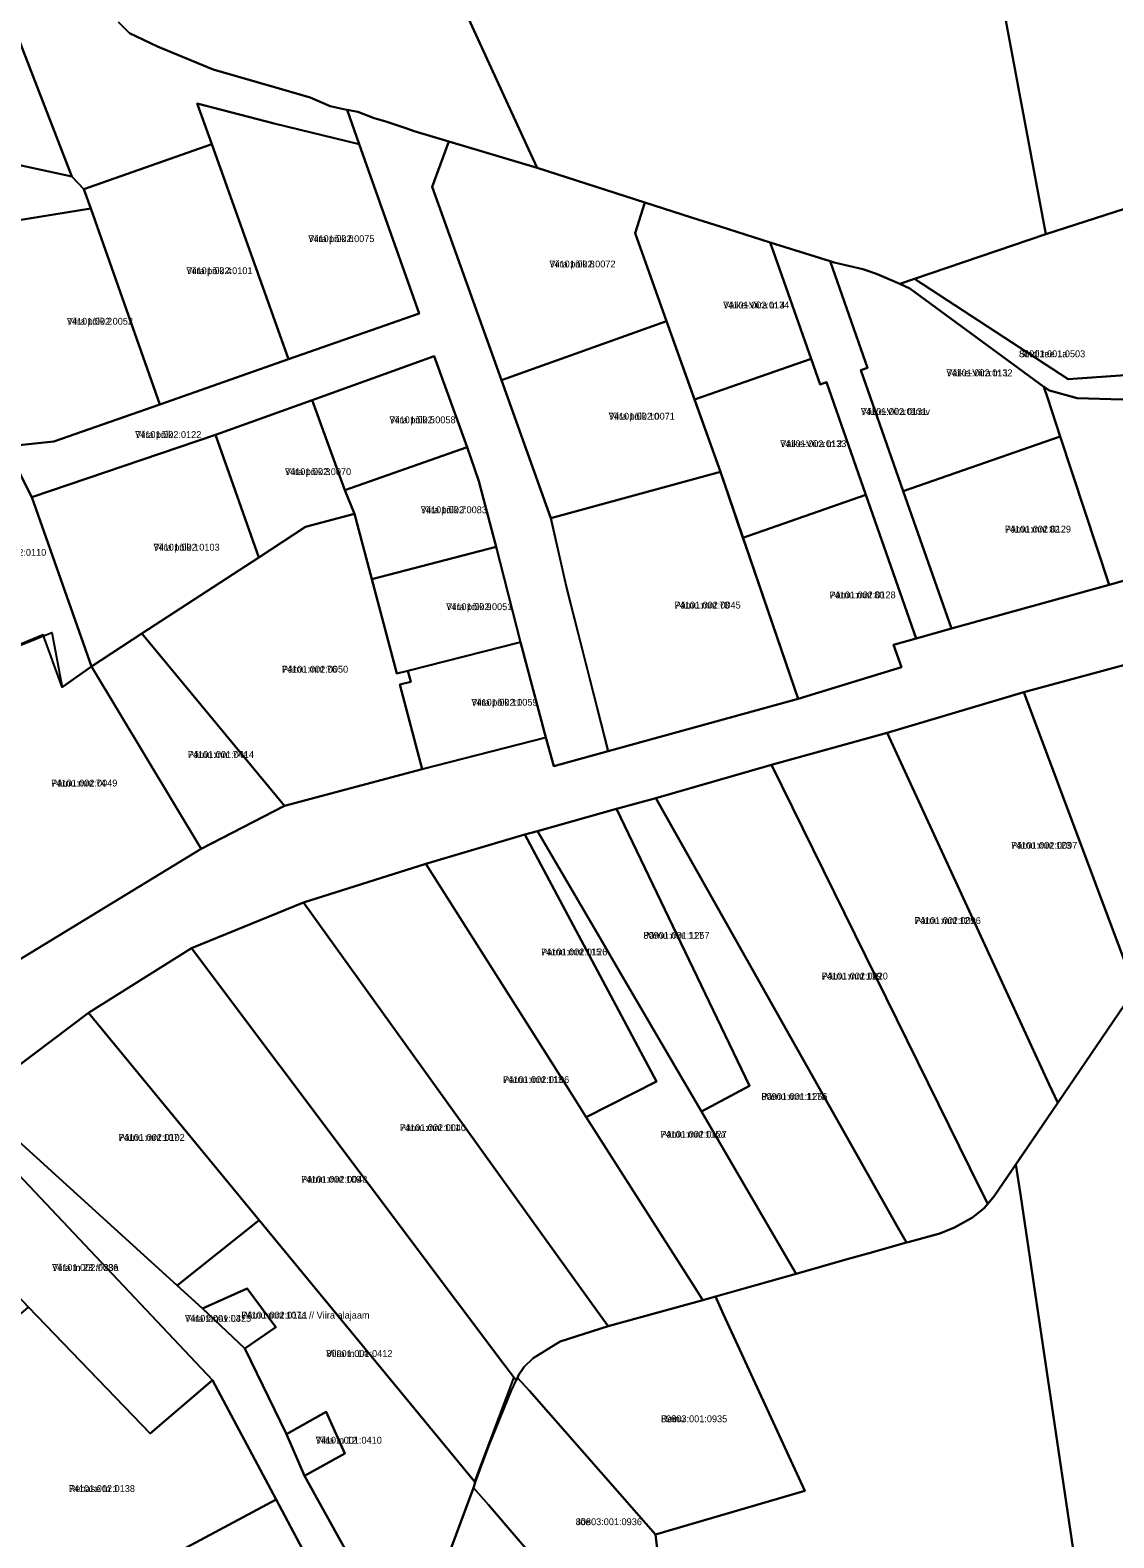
# Model space of a CAD drawing. Extents: x 524000 to 564260, y 6469338 to 6496391.
# Drawn here: x 539565.4 to 539802.9, y 6475121.9 to 6475452.4 of the extents above; entities that cross this region are included whole.
import ezdxf

# ---------------------------------------------------------------- set-up
doc = ezdxf.new("R2010")
doc.units = 0
for name, color, linetype in [('L_AADRESS', 7, 'Continuous'), ('PIIR', 7, 'Continuous'), ('TUNNUS', 7, 'Continuous')]:
    doc.layers.add(name, color=color, linetype=linetype)

msp = doc.modelspace()

# ---------------------------------------------------------------- linework, layer by layer
at = {"layer": 'PIIR'}
for points in [[(539758.44, 6475565.74), (539788.06, 6475407.65), (539759.28, 6475397.84), (539756, 6475396.72), (539750.91, 6475398.95), (539747.94, 6475399.94), (539741.65, 6475401.41), (539740.75, 6475401.69), (539727.65, 6475405.84), (539716.68, 6475409.31), (539713.15, 6475410.42), (539710.4, 6475411.29), (539700.11, 6475414.6), (539676.52, 6475422.21), (539674.67, 6475426.25), (539632.78, 6475517.5)], [(539944.83, 6475550.52), (539939.93, 6475424.76), (539893.58, 6475425.97), (539843.89, 6475430.55), (539837.9, 6475423.73), (539788.06, 6475407.65), (539758.44, 6475565.74)], [(539632.78, 6475517.5), (539674.67, 6475426.25), (539676.52, 6475422.21), (539657.18, 6475427.97), (539649.61, 6475430.22), (539647.73, 6475430.87), (539646.89, 6475431.16), (539645.11, 6475431.77), (539643.36, 6475432.37), (539640.79, 6475433.04), (539637.22, 6475434.42), (539634.87, 6475434.87), (539634.08, 6475435.02), (539631.18, 6475435.72), (539626.79, 6475437.63), (539620, 6475439.58), (539605.5, 6475443.71), (539593.35, 6475448.75), (539587.21, 6475451.69), (539584.75, 6475454.08)], [(539584.75, 6475454.08), (539587.21, 6475451.69), (539593.35, 6475448.75), (539605.5, 6475443.71), (539620, 6475439.58), (539626.79, 6475437.63), (539631.18, 6475435.72), (539634.08, 6475435.02), (539634.87, 6475434.87), (539637.56, 6475427.34), (539618.91, 6475431.9), (539602.06, 6475436.31), (539605.25, 6475427.37), (539577.22, 6475417.54), (539574.57, 6475420.29), (539559.71, 6475458.6)], [(539562.28, 6475361.31), (539570.64, 6475362.17), (539593.81, 6475370.3), (539622.08, 6475380.22), (539650.69, 6475390.25), (539637.56, 6475427.34), (539634.87, 6475434.87), (539637.22, 6475434.42), (539640.79, 6475433.04), (539643.36, 6475432.37), (539645.11, 6475431.77), (539646.89, 6475431.16), (539647.73, 6475430.87), (539649.61, 6475430.22), (539657.18, 6475427.97), (539653.52, 6475418.02), (539668.74, 6475375.62), (539679.57, 6475345.43), (539683.08, 6475329.78), (539692.11, 6475294.35), (539680.22, 6475291.07), (539678.43, 6475297.31), (539672.92, 6475318.2), (539667.57, 6475339.12), (539663.79, 6475353.49), (539661.17, 6475360.93), (539654, 6475380.89), (539627.2, 6475371.27), (539606.06, 6475363.69), (539565.76, 6475349.97), (539560.27, 6475360.93)], [(539557.87, 6475245.52), (539602.92, 6475272.93), (539621.14, 6475282.34), (539651.35, 6475290.37), (539678.43, 6475297.31), (539680.22, 6475291.07), (539692.11, 6475294.35), (539733.73, 6475305.77), (539756.41, 6475312.76), (539754.62, 6475317.65), (539759.6, 6475319.04), (539767.33, 6475321.19), (539801.89, 6475330.81), (539804.79, 6475331.61)], [(539825.05, 6475318.59), (539783.21, 6475307.29), (539753.26, 6475298.36), (539727.91, 6475291.35), (539702.52, 6475284.02), (539693.91, 6475281.72), (539676.62, 6475276.83), (539673.86, 6475276.05), (539652.11, 6475269.61), (539625.32, 6475261.18), (539600.82, 6475251.16), (539578.24, 6475236.96), (539554.03, 6475218.82), (539549.38, 6475215.78), (539535.08, 6475204.14), (539505.71, 6475181.68), (539504.39, 6475180.77), (539481.3, 6475162.97), (539462.39, 6475148.47), (539464.3, 6475146.34), (539456.7, 6475140.24), (539431.73, 6475120.22)]]:
    msp.add_lwpolyline(points, dxfattribs=at)
for points in [[(539529.14, 6475430.13), (539518.89, 6475431.12), (539522, 6475438.19), (539528.25, 6475452.4), (539559.71, 6475458.6), (539574.57, 6475420.29)], [(539605.25, 6475427.37), (539602.06, 6475436.31), (539618.91, 6475431.9), (539637.56, 6475427.34), (539650.69, 6475390.25), (539622.08, 6475380.22)], [(539518.89, 6475431.12), (539529.14, 6475430.13), (539574.57, 6475420.29), (539577.22, 6475417.54), (539578.69, 6475413.3), (539557.02, 6475409.74), (539553.12, 6475408.9), (539524.1, 6475406.02), (539521.82, 6475405.77)], [(539653.52, 6475418.02), (539657.18, 6475427.97), (539676.52, 6475422.21), (539700.11, 6475414.6), (539698.02, 6475407.87), (539704.92, 6475388.54), (539668.74, 6475375.62)], [(539578.69, 6475413.3), (539577.22, 6475417.54), (539605.25, 6475427.37), (539622.08, 6475380.22), (539593.81, 6475370.3)], [(539759.28, 6475397.84), (539788.06, 6475407.65), (539837.9, 6475423.73), (539846.99, 6475379.63), (539841.82, 6475379.26), (539792.94, 6475375.83)], [(539578.69, 6475413.3), (539593.81, 6475370.3), (539570.64, 6475362.17), (539562.28, 6475361.31), (539553.12, 6475408.9), (539557.02, 6475409.74)], [(539728.81, 6475402.52), (539736.57, 6475380.35), (539711.04, 6475371.42), (539704.92, 6475388.54), (539698.02, 6475407.87), (539700.11, 6475414.6), (539710.4, 6475411.29), (539713.15, 6475410.42), (539716.68, 6475409.31), (539727.65, 6475405.84)], [(539741.84, 6475398.59), (539748.93, 6475378.32), (539747.52, 6475377.82), (539756.79, 6475351.3), (539767.33, 6475321.19), (539759.6, 6475319.04), (539748.58, 6475350.53), (539739.96, 6475375.18), (539738.55, 6475374.69), (539736.57, 6475380.35), (539728.81, 6475402.52), (539727.65, 6475405.84), (539740.75, 6475401.69)], [(539750.91, 6475398.95), (539756, 6475396.72), (539758.21, 6475395.76), (539787.62, 6475374.19), (539788.46, 6475371.61), (539791.2, 6475363.29), (539756.79, 6475351.3), (539747.52, 6475377.82), (539748.93, 6475378.32), (539741.84, 6475398.59), (539740.75, 6475401.69), (539741.65, 6475401.41), (539747.94, 6475399.94)], [(539759.28, 6475397.84), (539792.94, 6475375.83), (539841.82, 6475379.26), (539844.69, 6475371.08), (539847.26, 6475363.5), (539844.46, 6475366.5), (539837.21, 6475370.03), (539827.39, 6475373.01), (539821.79, 6475373.74), (539815.93, 6475372.76), (539804.75, 6475371.39), (539794.89, 6475371.71), (539788.87, 6475373.37), (539787.62, 6475374.19), (539758.21, 6475395.76), (539756, 6475396.72)], [(539668.74, 6475375.62), (539704.92, 6475388.54), (539716.7, 6475355.58), (539679.57, 6475345.43)], [(539627.2, 6475371.27), (539654, 6475380.89), (539661.17, 6475360.93), (539634.42, 6475351.5)], [(539736.57, 6475380.35), (539738.55, 6475374.69), (539739.96, 6475375.18), (539748.58, 6475350.53), (539721.65, 6475341.11), (539716.7, 6475355.58), (539711.04, 6475371.42)], [(539854.91, 6475343.37), (539854.02, 6475343.16), (539804.79, 6475331.61), (539801.89, 6475330.81), (539791.2, 6475363.29), (539788.46, 6475371.61), (539787.62, 6475374.19), (539788.87, 6475373.37), (539794.89, 6475371.71), (539804.75, 6475371.39), (539815.93, 6475372.76), (539821.79, 6475373.74), (539827.39, 6475373.01), (539837.21, 6475370.03), (539844.46, 6475366.5), (539847.26, 6475363.5)], [(539615.56, 6475336.75), (539606.06, 6475363.69), (539627.2, 6475371.27), (539634.42, 6475351.5), (539636.48, 6475346.33), (539625.76, 6475343.53)], [(539565.76, 6475349.97), (539606.06, 6475363.69), (539615.56, 6475336.75), (539589.87, 6475320.14), (539578.83, 6475312.86)], [(539791.2, 6475363.29), (539801.89, 6475330.81), (539767.33, 6475321.19), (539756.79, 6475351.3)], [(539560.27, 6475360.93), (539565.76, 6475349.97), (539578.83, 6475312.86), (539572.41, 6475308.38), (539568.26, 6475319.86), (539539.55, 6475307.99), (539534.36, 6475306.01), (539530.08, 6475356.89)], [(539636.48, 6475346.33), (539634.42, 6475351.5), (539661.17, 6475360.93), (539663.79, 6475353.49), (539667.57, 6475339.12), (539640.28, 6475332.03)], [(539682.96, 6475330.42), (539679.57, 6475345.43), (539716.7, 6475355.58), (539733.73, 6475305.77), (539692.11, 6475294.35)], [(539748.58, 6475350.53), (539759.6, 6475319.04), (539754.62, 6475317.65), (539756.41, 6475312.76), (539733.73, 6475305.77), (539722.22, 6475339.45), (539721.65, 6475341.11)], [(539646.43, 6475308.93), (539651.35, 6475290.37), (539621.14, 6475282.34), (539589.87, 6475320.14), (539615.56, 6475336.75), (539625.76, 6475343.53), (539636.48, 6475346.33), (539640.28, 6475332.03), (539645.78, 6475311.35), (539648.2, 6475311.96), (539648.85, 6475309.55)], [(539645.78, 6475311.35), (539640.28, 6475332.03), (539667.57, 6475339.12), (539672.92, 6475318.2), (539648.19, 6475311.96)], [(539578.83, 6475312.86), (539602.92, 6475272.93), (539557.87, 6475245.52), (539537.14, 6475277.55), (539539.55, 6475307.99), (539570.19, 6475320.31), (539572.41, 6475308.38)], [(539578.83, 6475312.86), (539589.87, 6475320.14), (539621.14, 6475282.34), (539602.92, 6475272.93)], [(539648.19, 6475311.96), (539672.92, 6475318.2), (539678.43, 6475297.31), (539651.35, 6475290.37), (539646.41, 6475308.92), (539648.83, 6475309.54)], [(539783.21, 6475307.29), (539825.05, 6475318.59), (539830.04, 6475301.92), (539833.22, 6475291.26), (539835.47, 6475283.75), (539823.14, 6475265.07), (539823, 6475264.86), (539807.6, 6475242.18), (539806.03, 6475246.38)], [(539783.21, 6475307.29), (539806.03, 6475246.38), (539807.6, 6475242.18), (539790.66, 6475217.23), (539788.8, 6475221.26), (539753.26, 6475298.36)], [(539753.26, 6475298.36), (539788.8, 6475221.26), (539790.66, 6475217.23), (539776.71, 6475196.77), (539775.29, 6475195.12), (539773.67, 6475198.4), (539727.91, 6475291.35)], [(539755.61, 6475189.94), (539702.52, 6475284.02), (539727.91, 6475291.35), (539773.67, 6475198.4), (539775.29, 6475195.12), (539774.49, 6475194.19), (539771.96, 6475192.14), (539768.02, 6475189.95), (539764.82, 6475188.64), (539757.84, 6475186.75), (539757.47, 6475186.65)], [(539723.07, 6475220.95), (539693.91, 6475281.72), (539702.52, 6475284.02), (539755.61, 6475189.94), (539757.47, 6475186.65), (539749.04, 6475184.26), (539744.47, 6475182.97), (539733.34, 6475179.79), (539733.3, 6475179.78), (539731.35, 6475183.12), (539712.53, 6475215.34)], [(539690.86, 6475252.49), (539676.62, 6475276.83), (539693.91, 6475281.72), (539723.07, 6475220.95), (539712.53, 6475215.34), (539707.34, 6475224.21), (539694.61, 6475246.05)], [(539652.11, 6475269.61), (539673.86, 6475276.05), (539702.7, 6475221.95), (539687.32, 6475214.13), (539682.95, 6475221.01)], [(539702.7, 6475221.95), (539673.86, 6475276.05), (539676.62, 6475276.83), (539690.86, 6475252.49), (539694.61, 6475246.05), (539707.34, 6475224.21), (539712.53, 6475215.34), (539731.35, 6475183.12), (539733.3, 6475179.78), (539712.82, 6475174.03), (539710.71, 6475177.34), (539687.32, 6475214.13)], [(539652.11, 6475269.61), (539682.95, 6475221.01), (539687.32, 6475214.13), (539710.71, 6475177.34), (539712.82, 6475174.03), (539692.08, 6475168.27), (539689.75, 6475171.52), (539678.9, 6475186.61), (539625.32, 6475261.18)], [(539831.16, 6474869.16), (539782.58, 6475196.75), (539781.45, 6475203.72), (539790.66, 6475217.23), (539807.6, 6475242.18), (539823, 6475264.86), (539826.64, 6475263.44), (539876.07, 6475242.79), (539920.24, 6475224.35), (539955.56, 6475209.05), (539974.27, 6474933.88), (539974.31, 6474933.36)], [(539600.82, 6475251.16), (539625.32, 6475261.18), (539678.9, 6475186.61), (539689.75, 6475171.52), (539692.08, 6475168.27), (539681.58, 6475164.91), (539675.7, 6475161.29), (539673.7, 6475159.42), (539672.46, 6475157.54), (539672.2, 6475156.98), (539671.93, 6475156.39), (539669, 6475160.3), (539659.12, 6475173.46)], [(539659.37, 6475138.39), (539615.58, 6475191.51), (539578.24, 6475236.96), (539600.82, 6475251.16), (539659.12, 6475173.46), (539669, 6475160.3), (539671.4, 6475157.1), (539662.79, 6475134.25)], [(539554.03, 6475218.82), (539578.24, 6475236.96), (539615.58, 6475191.51), (539597.66, 6475177.19), (539561.15, 6475210.35)], [(539605.37, 6475156.48), (539549.38, 6475215.78), (539554.03, 6475218.82), (539561.15, 6475210.35), (539597.66, 6475177.19), (539603.22, 6475172.2), (539612.5, 6475163.41), (539621.61, 6475144.62), (539625.52, 6475135.5), (539642.98, 6475104.01), (539647.08, 6475099.52), (539649.32, 6475097.06), (539649.25, 6475096.88), (539643.46, 6475081.48), (539641.9, 6475084.73), (539626.35, 6475117.08), (539619.33, 6475130.28)], [(539535.08, 6475204.14), (539549.38, 6475215.78), (539605.37, 6475156.48), (539591.7, 6475144.75), (539565.08, 6475172.46)], [(539707.43, 6475080.55), (539702.45, 6475122.64), (539735.2, 6475132.23), (539717.35, 6475170.84), (539715.66, 6475174.83), (539733.3, 6475179.78), (539733.34, 6475179.79), (539744.47, 6475182.97), (539749.04, 6475184.26), (539757.47, 6475186.65), (539757.84, 6475186.75), (539764.82, 6475188.64), (539768.02, 6475189.95), (539771.96, 6475192.14), (539774.49, 6475194.19), (539775.29, 6475195.12), (539776.71, 6475196.77), (539781.45, 6475203.72), (539782.58, 6475196.75), (539831.16, 6474869.16), (539763.32, 6474839.28), (539687.76, 6475058.65)], [(539603.22, 6475172.2), (539597.66, 6475177.19), (539615.58, 6475191.51), (539659.37, 6475138.39), (539662.79, 6475134.25), (539662.99, 6475134.01), (539662.56, 6475132.85), (539649.32, 6475097.06), (539647.08, 6475099.52), (539642.98, 6475104.01), (539625.52, 6475135.5), (539634.4, 6475140.4), (539630.3, 6475149.54), (539621.61, 6475144.62), (539612.5, 6475163.41), (539619.25, 6475168.07), (539612.97, 6475176.53)], [(539603.22, 6475172.2), (539612.97, 6475176.53), (539619.25, 6475168.07), (539612.5, 6475163.41)], [(539674.89, 6475154.13), (539672.2, 6475156.98), (539672.46, 6475157.54), (539673.7, 6475159.42), (539675.7, 6475161.29), (539681.58, 6475164.91), (539692.08, 6475168.27), (539712.82, 6475174.03), (539715.66, 6475174.83), (539717.35, 6475170.84), (539735.2, 6475132.23), (539702.45, 6475122.64)], [(539546.15, 6475091.47), (539544.25, 6475093.57), (539517.4, 6475123.15), (539538.81, 6475138.94), (539539.57, 6475139.5), (539534.11, 6475145.91), (539565.08, 6475172.46), (539591.7, 6475144.75), (539605.37, 6475156.48), (539619.33, 6475130.28), (539571.71, 6475104.85), (539566.99, 6475102.33), (539566.92, 6475102.34), (539561.62, 6475099.53)], [(539662.56, 6475132.85), (539662.99, 6475134.01), (539663.04, 6475134.13), (539664.06, 6475136.89), (539665.98, 6475142.03), (539670.93, 6475154.18), (539671.93, 6475156.39), (539672.2, 6475156.98), (539674.89, 6475154.13), (539702.45, 6475122.64), (539707.43, 6475080.55), (539665.86, 6475129.17)], [(539625.52, 6475135.5), (539621.61, 6475144.62), (539630.3, 6475149.54), (539634.4, 6475140.4)], [(539649.32, 6475097.06), (539662.56, 6475132.85), (539665.86, 6475129.17), (539707.43, 6475080.55), (539687.76, 6475058.65), (539656.29, 6475089.89), (539649.25, 6475096.88)], [(539566.99, 6475102.33), (539571.71, 6475104.85), (539619.33, 6475130.28), (539626.35, 6475117.08), (539586.17, 6475096.34), (539568.44, 6475087.13), (539562.88, 6475097.3), (539561.62, 6475099.53), (539566.92, 6475102.34)]]:
    msp.add_lwpolyline(points, close=True, dxfattribs=at)

# ---------------------------------------------------------------- texts
at = {"layer": 'L_AADRESS'}
for s, p in [('Viira põik 6', (539626.38, 6475405.9)), ('Viira põik 8', (539679.22, 6475400.35)), ('Viira põik 4', (539599.65, 6475398.88)), ('Väike-Viira tn 4', (539717.3, 6475391.36)), ('Viira põik 2', (539573.46, 6475387.8)), ('Sindi tee 1a', (539782.16, 6475380.67)), ('Väike-Viira tn 1', (539766.23, 6475376.5)), ('Viira põik 10', (539692.23, 6475366.99)), ('Väike-Viira tänav', (539747.49, 6475368.04)), ('Viira põik 5', (539644.17, 6475366.2)), ('Viira põik', (539588.43, 6475362.97)), ('Väike-Viira tn 2', (539729.81, 6475360.97)), ('Viira põik 3', (539621.27, 6475354.84)), ('Viira põik 7', (539651.03, 6475346.48)), ('Pärnu mnt 82', (539779.04, 6475342.24)), ('Viira põik 1', (539592.45, 6475338.28)), ('Pärnu mnt 80', (539740.62, 6475327.82)), ('Viira põik 9', (539656.6, 6475325.24)), ('Pärnu mnt 78', (539706.65, 6475325.59)), ('Pärnu mnt 76', (539620.61, 6475311.54)), ('Viira põik 11', (539662.12, 6475304.29)), ('Pärnu mnt 74a', (539599.98, 6475292.85)), ('Pärnu mnt 74', (539570.03, 6475286.58)), ('Pärnu mnt 123', (539780.43, 6475272.94)), ('Pärnu mnt 121', (539759.28, 6475256.45)), ('Pärnu mnt 117', (539699.84, 6475253.21)), ('Pärnu mnt 115', (539677.41, 6475249.57)), ('Pärnu mnt 119', (539738.91, 6475244.28)), ('Pärnu mnt 113', (539669.07, 6475221.59)), ('Pärnu mnt 117a', (539725.69, 6475217.89)), ('Pärnu mnt 107', (539584.8, 6475208.92)), ('Pärnu mnt 111', (539646.45, 6475211.06)), ('Pärnu mnt 115a', (539703.58, 6475209.61)), ('Pärnu mnt 109', (539624.82, 6475199.74)), ('Viira tn 23 // 23a', (539570.22, 6475180.4)), ('Viira tänav L3', (539599.35, 6475169.26)), ('Pärnu mnt 107a // Viira alajaam', (539611.71, 6475169.97)), ('Viira tn 14', (539630.32, 6475161.55)), ('Reinu', (539703.7, 6475147.25)), ('Viira tn 12', (539628, 6475142.56)), ('Rebase tn 1', (539573.89, 6475131.96)), ('Jõe', (539685, 6475124.69))]:
    msp.add_text(s, height=1.5, dxfattribs=at).set_placement(p)
at = {"layer": 'TUNNUS'}
for s, p in [('74101:002:0075', (539626.38, 6475405.9)), ('74101:002:0072', (539679.22, 6475400.35)), ('74101:002:0101', (539599.65, 6475398.88)), ('74101:002:0134', (539717.3, 6475391.36)), ('74101:002:0052', (539573.46, 6475387.8)), ('80901:001:0503', (539782.16, 6475380.67)), ('74101:002:0132', (539766.23, 6475376.5)), ('74101:002:0071', (539692.23, 6475366.99)), ('74101:002:0131', (539747.49, 6475368.04)), ('74101:002:0058', (539644.17, 6475366.2)), ('74101:002:0122', (539588.43, 6475362.97)), ('74101:002:0133', (539729.81, 6475360.97)), ('74101:002:0070', (539621.27, 6475354.84)), ('74101:002:0083', (539651.03, 6475346.48)), ('74101:002:0129', (539779.04, 6475342.24)), ('74101:002:0110', (539554.45, 6475337.15)), ('74101:002:0103', (539592.45, 6475338.28)), ('74101:002:0128', (539740.62, 6475327.82)), ('74101:002:0051', (539656.6, 6475325.24)), ('74101:002:0045', (539706.65, 6475325.59)), ('74101:002:0050', (539620.61, 6475311.54)), ('74101:002:0059', (539662.12, 6475304.29)), ('74101:001:0414', (539599.98, 6475292.85)), ('74101:002:0049', (539570.03, 6475286.58)), ('74101:002:0097', (539780.43, 6475272.94)), ('74101:002:0096', (539759.28, 6475256.45)), ('80901:001:1257', (539699.84, 6475253.21)), ('74101:002:0126', (539677.41, 6475249.57)), ('74101:002:0020', (539738.91, 6475244.28)), ('74101:002:0106', (539669.07, 6475221.59)), ('80901:001:1256', (539725.69, 6475217.89)), ('74101:002:0102', (539584.8, 6475208.92)), ('74101:002:0040', (539646.45, 6475211.06)), ('74101:002:0127', (539703.58, 6475209.61)), ('74101:002:0048', (539624.82, 6475199.74)), ('74101:002:0086', (539570.22, 6475180.4)), ('74101:001:0425', (539599.35, 6475169.26)), ('74101:002:0111', (539611.71, 6475169.97)), ('80901:001:0412', (539630.32, 6475161.55)), ('80803:001:0935', (539703.7, 6475147.25)), ('74101:001:0410', (539628, 6475142.56)), ('74101:002:0138', (539573.89, 6475131.96)), ('80803:001:0936', (539685, 6475124.69))]:
    msp.add_text(s, height=1.5, dxfattribs=at).set_placement(p)

doc.saveas('drawing.dxf')
